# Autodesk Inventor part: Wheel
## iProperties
Created: 2008-06
Part Number: Wheel
Document SubType Name: Modeling
Designer: CADCIM
Density: 1 g/cm^3
Author: CADCIM
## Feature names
1. Revolution1
2. Extrusion1
3. Fillet1
4. Fillet2
5. Chamfer1
6. Fillet3
7. Fillet4
8. Fillet5
9. Circular Pattern2
